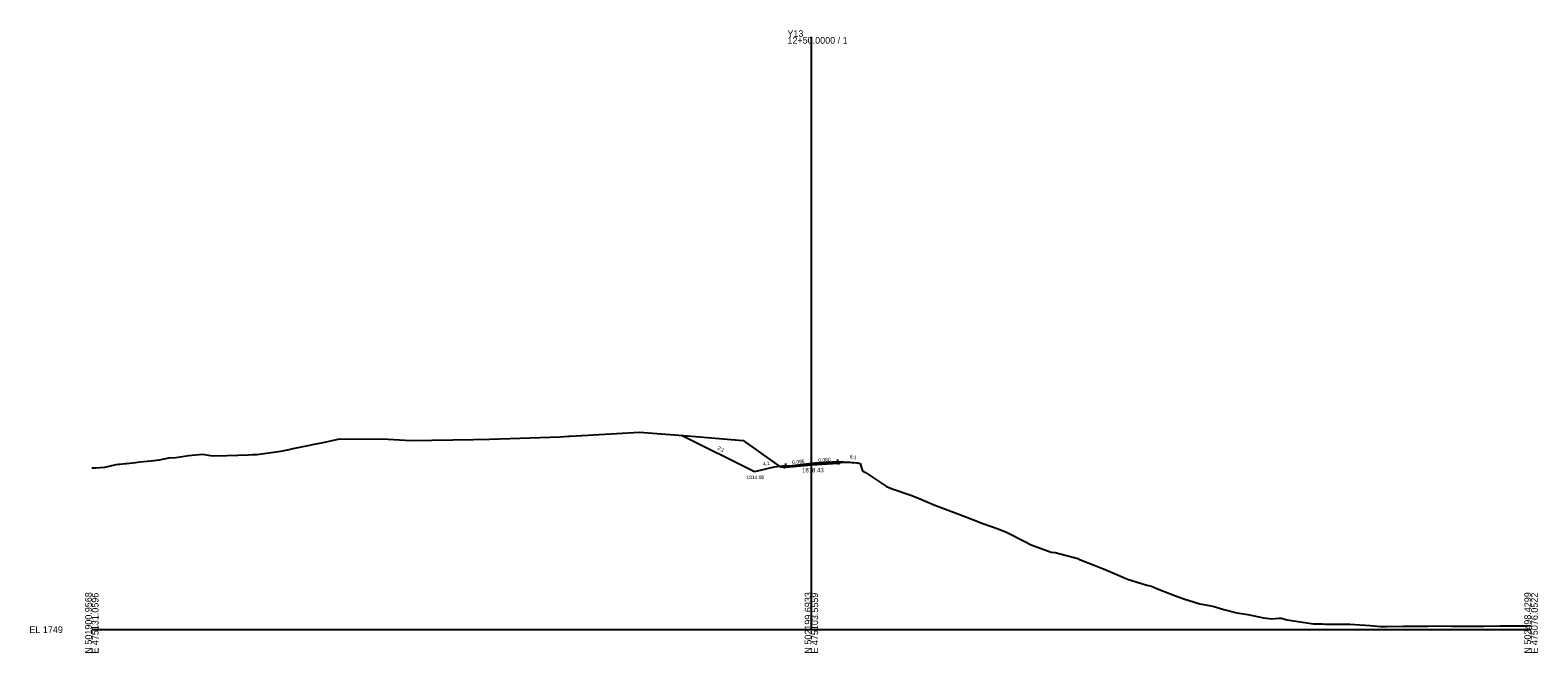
# Model space of a CAD drawing. Extents: x -126 to 503, y -10 to 2750.
# Drawn here: x -126 to 503, y 2490 to 2750 of the extents above; entities that cross this region are included whole.
import ezdxf

# ---------------------------------------------------------------- set-up
doc = ezdxf.new("R2010")
doc.units = 0
for name, color, linetype in [('Exist Cross Section Cell', 7, 'Continuous'), ('Exist XS Center Line Elevation Label', 7, 'Continuous'), ('Exist XS Ground Line', 7, 'Continuous'), ('Prop XS Ditch Slope Text', 7, 'Continuous'), ('Prop XS Ditch Standard Text', 7, 'Continuous'), ('Prop XS Dump Level', 7, 'Continuous'), ('Prop XS Earthwork Shape', 7, 'Continuous'), ('Prop XS EOT Tick Mark', 7, 'Continuous'), ('Prop XS Finish Grade', 7, 'Continuous'), ('Prop XS Finish Grade Earthwork', 7, 'Continuous'), ('Prop XS Finish Grade Pavement', 7, 'Continuous'), ('Prop XS Hydro Fill Slope Data', 7, 'Continuous'), ('Prop XS Hydro Typical Ditch Data', 7, 'Continuous'), ('Prop XS Pvmt Edge Slope', 7, 'Continuous'), ('Prop XS SE Text', 7, 'Continuous'), ('Prop XS Shoulder Borrow Shape', 7, 'Continuous'), ('Prop XS Side Slope Text', 7, 'Continuous'), ('Prop XS Subgrade Earthwork', 7, 'Continuous')]:
    doc.layers.add(name, color=color, linetype=linetype)

msp = doc.modelspace()

# ---------------------------------------------------------------- linework, layer by layer
at = {"layer": 'Exist Cross Section Cell'}
for p, q in [((200, 2500), (200, 2747.26)), ((-100, 2500), (200, 2500)), ((200, 2500), (500, 2500))]:
    msp.add_line(p, q, dxfattribs=at)
at = {"layer": 'Exist XS Ground Line'}
msp.add_lwpolyline([(-100, 2567.5), (-98.39, 2567.53), (-94.61, 2567.79), (-89.79, 2568.86), (-88.86, 2568.96), (-88.32, 2569.02), (-86.1, 2569.27), (-85.52, 2569.33), (-81.74, 2569.74), (-79.95, 2569.94), (-75.4, 2570.44), (-71.76, 2570.84), (-69.83, 2571.2), (-67.7, 2571.61), (-64.97, 2571.87), (-59.53, 2572.7), (-53.78, 2573.22), (-49.67, 2572.49), (-43.62, 2572.68), (-34.61, 2572.95), (-32.81, 2573.01), (-31.18, 2573.05), (-21.2, 2574.43), (-17.78, 2575.14), (-16.04, 2575.51), (-12.51, 2576.24), (-9.8, 2576.81), (-7.35, 2577.32), (-4.24, 2577.96), (-2.29, 2578.37), (1.45, 2579.15), (2.67, 2579.4), (3.38, 2579.55), (23.36, 2579.47), (33.11, 2578.89), (59.2, 2579.3), (65.87, 2579.43), (95.27, 2580.49), (98.75, 2580.65), (99.3, 2580.77), (101.93, 2580.89), (128.32, 2582.42), (148.36, 2580.83), (171.61, 2578.94), (186.05, 2568.61), (187.21, 2567.75), (189.81, 2568.28), (190.82, 2568.39), (200, 2569.43), (200.59, 2569.5), (201.49, 2569.56), (210.89, 2570.1), (218.85, 2569.57), (219.46, 2569.54), (219.77, 2569.51), (220.32, 2569.25), (221.32, 2566.29), (222.57, 2565.49), (231.36, 2559.75), (233.63, 2558.79), (241.4, 2556.04), (244.69, 2554.83), (251.43, 2551.97), (257.04, 2549.78), (261.48, 2548.14), (266.81, 2546.08), (271.52, 2544.25), (277.87, 2542.08), (281.56, 2540.57), (288.93, 2536.78), (291.59, 2535.39), (299.99, 2532.35), (301.63, 2532.13), (311.05, 2529.63), (311.68, 2529.31), (312.2, 2529.06), (317.87, 2526.93), (321.39, 2525.54), (321.72, 2525.43), (330.58, 2521.64), (331.75, 2521.12), (339.77, 2518.58), (341.79, 2518.11), (344.23, 2517.01), (351.84, 2514.06), (355.28, 2512.89), (361.87, 2510.82), (367.35, 2509.75), (371.91, 2508.46), (377.4, 2507), (381.95, 2506.25), (388.47, 2504.91), (392, 2504.5), (394.93, 2504.74), (395.95, 2504.75), (397.31, 2504.36), (397.62, 2504.26), (398.33, 2504.06), (409.31, 2502.44), (413.05, 2502.37), (414.27, 2502.3), (415.85, 2502.35), (424.45, 2502.23), (432.92, 2501.7), (437.38, 2501.28), (439.76, 2501.25), (446.79, 2501.38), (450.82, 2501.39), (456.84, 2501.51), (461.84, 2501.6), (466.88, 2501.39), (472.94, 2501.49), (476.93, 2501.5), (480.24, 2501.5), (486.97, 2501.56), (489.44, 2501.61), (497.02, 2501.62), (498.63, 2501.59), (500, 2501.72)], dxfattribs=at)
at = {"layer": 'Prop XS Dump Level'}
for p, q in [((189.32, 2568.26), (200, 2569.28)), ((200, 2569.28), (210.97, 2569.93))]:
    msp.add_line(p, q, dxfattribs=at)
at = {"layer": 'Prop XS Earthwork Shape'}
for points in [[(176.32, 2565.79), (145.84, 2581.03), (148.36, 2580.83), (171.61, 2578.94), (186.05, 2568.61), (186.83, 2568.02), (184.32, 2567.79)], [(187.98, 2568.13), (186.83, 2568.02), (187.21, 2567.75), (188.17, 2567.94)], [(210.89, 2570.1), (213.38, 2569.93), (212.23, 2569.93), (211.6, 2569.3), (210.97, 2569.27), (200, 2568.61), (189.32, 2567.59), (188.58, 2567.52), (188.17, 2567.94), (189.81, 2568.28), (190.82, 2568.39), (200, 2569.43), (200.59, 2569.5), (201.49, 2569.56)], [(215.97, 2569.93), (217.66, 2569.65), (213.38, 2569.93)]]:
    msp.add_lwpolyline(points, close=True, dxfattribs=at)
at = {"layer": 'Prop XS EOT Tick Mark'}
for p, q in [((210.97, 2569.93), (210.97, 2570.93)), ((189.32, 2568.26), (189.32, 2569.26))]:
    msp.add_line(p, q, dxfattribs=at)
at = {"layer": 'Prop XS Finish Grade'}
for p, q in [((189.32, 2568.26), (187.98, 2568.13)), ((210.97, 2569.93), (212.23, 2569.93))]:
    msp.add_line(p, q, dxfattribs=at)
at = {"layer": 'Prop XS Finish Grade Earthwork'}
for p, q in [((176.32, 2565.79), (145.84, 2581.03)), ((184.32, 2567.79), (176.32, 2565.79)), ((187.98, 2568.13), (184.32, 2567.79)), ((212.23, 2569.93), (215.97, 2569.93)), ((215.97, 2569.93), (217.66, 2569.65))]:
    msp.add_line(p, q, dxfattribs=at)
at = {"layer": 'Prop XS Finish Grade Pavement'}
for p, q in [((189.32, 2568.26), (200, 2569.28)), ((200, 2569.28), (210.97, 2569.93))]:
    msp.add_line(p, q, dxfattribs=at)
at = {"layer": 'Prop XS Hydro Fill Slope Data'}
msp.add_line((215.97, 2569.93), (217.66, 2569.65), dxfattribs=at)
at = {"layer": 'Prop XS Hydro Typical Ditch Data'}
for p, q in [((176.32, 2565.79), (145.84, 2581.03)), ((184.32, 2567.79), (176.32, 2565.79))]:
    msp.add_line(p, q, dxfattribs=at)
at = {"layer": 'Prop XS Pvmt Edge Slope'}
for p, q in [((189.32, 2568.26), (188.58, 2567.52)), ((210.97, 2569.93), (211.6, 2569.3))]:
    msp.add_line(p, q, dxfattribs=at)
at = {"layer": 'Prop XS Shoulder Borrow Shape'}
for points in [[(189.32, 2568.26), (188.58, 2567.52), (187.98, 2568.13)], [(211.6, 2569.3), (212.23, 2569.93), (210.97, 2569.93)]]:
    msp.add_lwpolyline(points, close=True, dxfattribs=at)
at = {"layer": 'Prop XS Subgrade Earthwork'}
for p, q in [((188.58, 2567.52), (187.98, 2568.13)), ((189.32, 2567.59), (188.58, 2567.52)), ((200, 2568.61), (189.32, 2567.59)), ((210.97, 2569.27), (200, 2568.61)), ((210.97, 2569.27), (211.6, 2569.3)), ((211.6, 2569.3), (212.23, 2569.93))]:
    msp.add_line(p, q, dxfattribs=at)

# ---------------------------------------------------------------- texts
at = {"layer": 'Exist Cross Section Cell'}
for s, p in [('Y13', (190, 2747.26)), ('12+50.0000 / 1', (190, 2744.46)), ('EL 1749', (-126, 2498.6))]:
    msp.add_text(s, height=2.8, dxfattribs=at).set_placement(p)
for s, p in [('N 501900.9568', (-100, 2490)), ('E 475131.0596', (-97.2, 2490)), ('N 502199.6933', (200, 2490)), ('E 475103.5559', (202.8, 2490)), ('N 502498.4299', (500, 2490)), ('E 475076.0522', (502.8, 2490))]:
    msp.add_text(s, height=2.8, rotation=90, dxfattribs=at).set_placement(p)
at = {"layer": 'Exist XS Center Line Elevation Label'}
msp.add_text('1818.43', height=1.8, dxfattribs=at).set_placement((196.12, 2565.63))
at = {"layer": 'Prop XS Ditch Slope Text'}
msp.add_text('4:1', height=1.5, rotation=14.03501, dxfattribs=at).set_placement((179.96, 2568.24))
at = {"layer": 'Prop XS Ditch Standard Text'}
msp.add_text('1814.80', height=1.5, dxfattribs=at).set_placement((172.87, 2562.79))
at = {"layer": 'Prop XS Dump Level'}
for p in [(184.32, 2567.75), (215.97, 2569.89)]:
    msp.add_text('Case1', height=0.04, dxfattribs=at).set_placement(p)
at = {"layer": 'Prop XS SE Text'}
for s, rotation, p in [('0.095', 5.42563, (192.07, 2569.02)), ('0.060', 3.43363, (202.87, 2569.95))]:
    msp.add_text(s, height=1.5, rotation=rotation, dxfattribs=at).set_placement(p)
at = {"layer": 'Prop XS Side Slope Text'}
for s, rotation, p in [('2:1', 333.43705, (160.68, 2575.28)), ('6:1', 350.53768, (215.89, 2571.47))]:
    msp.add_text(s, height=1.5, rotation=rotation, dxfattribs=at).set_placement(p)

doc.saveas('drawing.dxf')
